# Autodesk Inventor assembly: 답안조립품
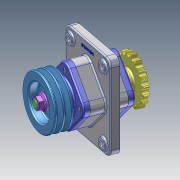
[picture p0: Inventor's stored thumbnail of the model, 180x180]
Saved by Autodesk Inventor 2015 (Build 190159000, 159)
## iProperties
Created: 2026-07
Part Number: 답안조립품
Document SubType Name: Assembly
Designer: user
Author: user
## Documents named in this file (12)
- C:\Users\user\Desktop\이지현\760705V1004\답안조립품.iam
- C:\Users\user\Desktop\이지현\760705V1004\본체.ipt
- C:\Users\user\Desktop\이지현\760705V1004\가져온 구성요소\6각 구멍붙이 볼트 M6x16\6각 구멍붙이 볼트 M6x16.ipt
- C:\Users\user\Desktop\이지현\760705V1004\가져온 구성요소\6각 플랜지 너트 M16\6각 플랜지 너트 M16.ipt
- C:\Users\user\Desktop\이지현\760705V1004\가져온 구성요소\V-벨트풀리\V-벨트풀리.ipt
- C:\Users\user\Desktop\이지현\760705V1004\가져온 구성요소\깊은 홈 볼 베어링 6206\깊은 홈 볼 베어링 6206.ipt
- C:\Users\user\Desktop\이지현\760705V1004\가져온 구성요소\오일 실 30 45 8\오일 실 30 45 8.ipt
- C:\Users\user\Desktop\이지현\760705V1004\가져온 구성요소\체인 스프로킷\체인 스프로킷.ipt
- C:\Users\user\Desktop\이지현\760705V1004\가져온 구성요소\축\축.ipt
- C:\Users\user\Desktop\이지현\760705V1004\가져온 구성요소\칼라\칼라.ipt
- C:\Users\user\Desktop\이지현\760705V1004\가져온 구성요소\커버\커버.ipt
- C:\Users\user\Desktop\이지현\760705V1004\가져온 구성요소\평행 키 6x6x20\평행 키 6x6x20.ipt
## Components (11 placed, 3 different names)
1. 6각 구멍붙이 볼트 M6x16:1
2. 6각 플랜지 너트 M16:1
3. V-벨트풀리:1
4. 6각 플랜지 너트 M16:2
5. 6각 구멍붙이 볼트 M6x16:2
6. 6각 구멍붙이 볼트 M6x16:3
7. 6각 구멍붙이 볼트 M6x16:4
8. 6각 구멍붙이 볼트 M6x16:5
9. 6각 구멍붙이 볼트 M6x16:6
10. 6각 구멍붙이 볼트 M6x16:7
11. 6각 구멍붙이 볼트 M6x16:8
